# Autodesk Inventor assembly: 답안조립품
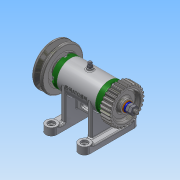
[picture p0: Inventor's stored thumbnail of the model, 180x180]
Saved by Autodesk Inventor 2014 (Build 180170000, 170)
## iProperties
Created: 2015-11
Part Number: 답안조립품
Document SubType Name: Assembly
Designer: 103-15
Author: 103-15
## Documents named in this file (16)
- C:\Users\103-15\Desktop\451110V1055\답안조립품.iam
- C:\Users\103-15\Desktop\451110V1055\1-본체.ipt
- C:\Users\103-15\Desktop\451110V1055\V벨트풀리.ipt
- C:\Users\103-15\Desktop\451110V1055\너트 M 8.ipt
- C:\Users\103-15\Desktop\451110V1055\니플 M 6 x 0.75.ipt
- C:\Users\103-15\Desktop\451110V1055\베어링 15 x 32 x 9.ipt
- C:\Users\103-15\Desktop\451110V1055\볼트 M 6 x 8.ipt
- C:\Users\103-15\Desktop\451110V1055\볼트 M4 x 12.ipt
- C:\Users\103-15\Desktop\451110V1055\스퍼기어.ipt
- C:\Users\103-15\Desktop\451110V1055\스프링와셔 8.ipt
- C:\Users\103-15\Desktop\451110V1055\오일 실 15 25 7.ipt
- C:\Users\103-15\Desktop\451110V1055\와셔 6x11.5.ipt
- C:\Users\103-15\Desktop\451110V1055\와셔 8x17.ipt
- C:\Users\103-15\Desktop\451110V1055\축.ipt
- C:\Users\103-15\Desktop\451110V1055\커버.ipt
- C:\Users\103-15\Desktop\451110V1055\키 3 x 3 x 12.ipt
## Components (12 placed, 4 different names)
1. 1-본체:1
2. V벨트풀리:1 — 각도:4
3. KS B 2023 6002 - 15 x 32 x 9:1
4. KS B 2023 6002 - 15 x 32 x 9:2
5. ISO 4762 M4 x 12:2
6. ISO 4762 M4 x 12:3
7. ISO 4762 M4 x 12:4
8. ISO 4762 M4 x 12:5
9. ISO 4762 M4 x 12:1
10. ISO 4762 M4 x 12:6
11. ISO 4762 M4 x 12:7
12. ISO 4762 M4 x 12:8
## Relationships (1: Angle 1)
- 각도:4 [Angle]: V벨트풀리:1
## Named parameters: d43_d4 = 0, d44_d5 = 0
